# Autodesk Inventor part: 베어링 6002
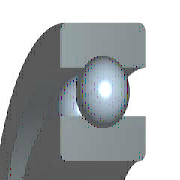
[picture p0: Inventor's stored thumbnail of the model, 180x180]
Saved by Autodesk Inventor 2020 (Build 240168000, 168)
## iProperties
Created: 2012-02
Part Number: 베어링 6002
Material: 강철, 연강
Description: 깊은 그루브 볼 베어링
Document SubType Name: Modeling
Standard: KS B 2023
Designer: mduedu
Standards Organization: KS
Language: ko-KR
Size Designation: 6002 - 15 x 32 x 9
Categories: <MemberInstance><Categories><Category DisplayName="샤프트 부품" InternalName="7f7aeb1f-a693-4053-b835-cee3144e0d98" Mnemonic="SHFT"><Category DisplayName="베어링" Inter
Density: 7.86 g/cm^3
Mass: 29.8124 g
Surface Area: 39.9079 cm^2
Volume: 3.79293 cm^3
Appearance: 노란색
IsCustomPart: 0
Author: mduedu
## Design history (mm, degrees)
sketch "스케치" dims "d0" = 4.42 (= -0.26 x WD + 0.26 x BD)
  geometry: L1 (2.29, 11.75)-(6.71, 11.75); L2 (4.5, 11.75)-(4.5, 9.54); L3 (4.5, 11.75)-(4.5, 13.96); L4 (2.858, 10.271)-(0, 10.271); L5 (0, 7.5)-(9, 7.5); L6 (2.858, 13.229)-(0, 13.229); L7 (0, 16)-(9, 16); L8 (9, 7.5)-(9, 10.271); L9 (6.142, 10.271)-(9, 10.271); L10 (6.142, 13.229)-(9, 13.229); L11 (9, 16)-(9, 13.229); L12 (-1.4, 0)-(8.4, 0) reference; L13 (0, -0.3)-(0, 5.3) reference
  constraints: 22 end point, 4 point on line, 2 collinear, 2 perpendicular, 2 symmetric about line, 1 midpoint, 1 parallel, 14 other
  dimensions: "d9" = 15 diameter of L5 L12 (= WD); "d11" = 32 diameter of L7 L12 (= BD); "d12" = 9 distance between parallel lines of L8 L13 (= KB); "d13" = 20.542 diameter of L9 L12 (= 0.326 x BD + 0.674 x WD)
revolve "본체" stored, may be unused: angle "d6" = 90 deg
revolve "볼" stored, may be unused: angle "d7" = 90 deg
pattern_circular "IDS_ARRAYBALL[SIMPL:T]" dims angle "d3" = 360 deg
body "Solid1"
fillet "모깎기1" dims "d1" = 0.3 (= KRS)
other parameters: "WD" = 15 [user parameter; used in 5 equation terms], "BD" = 32 [user parameter; used in 5 equation terms], "KB" = 9 [user parameter; used in 1 equation term], "KRS" = 0.3 [user parameter; used in 1 equation term], "d4" = 0, "d5" = 0, "d8" = 0, "d14" = 0, "d15" = 0, "BBA" = 0 [user parameter], "BC0" = 2850000 [user parameter], "BC" = 5590000 [user parameter], "BR" = 16 (= 0.5 x BD) [user parameter], "WR" = 7.5 (= 0.5 x WD) [user parameter]
